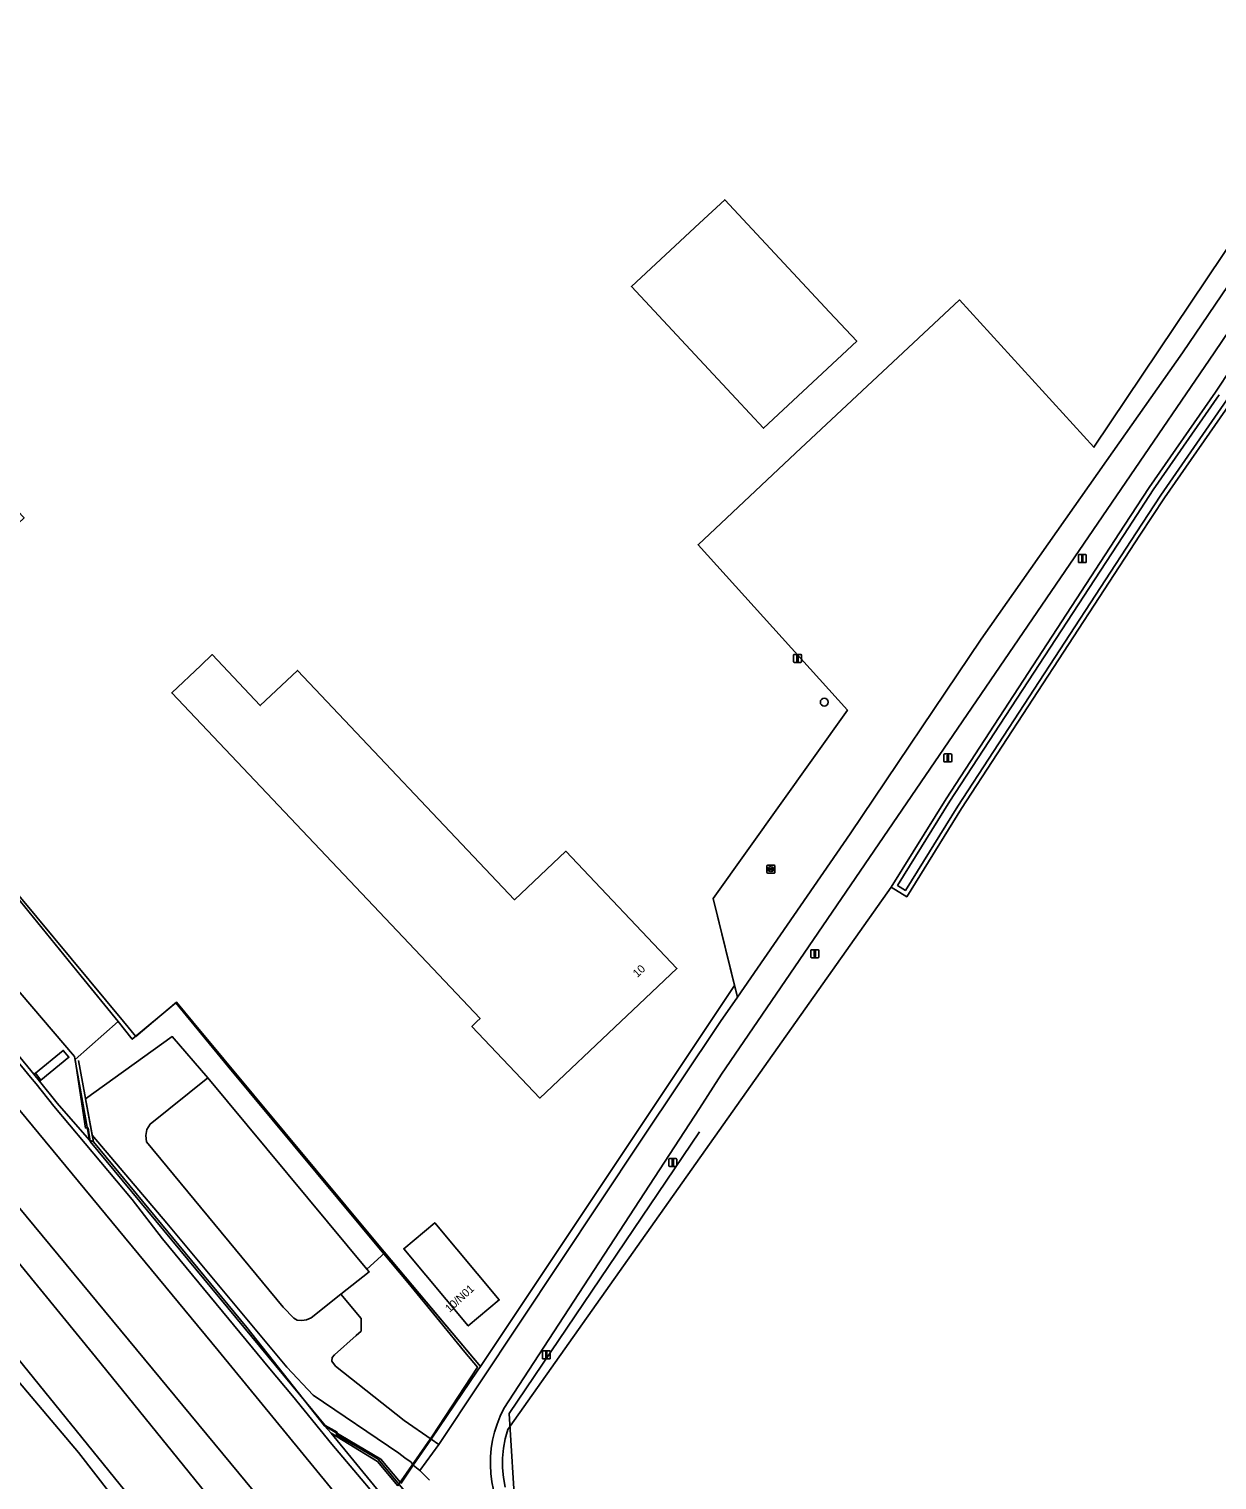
# Model space of a CAD drawing. Extents: x 158132 to 159664, y 385256 to 387218.
# Drawn here: x 158916.2 to 159064.7, y 385692.7 to 385874 of the extents above; entities that cross this region are included whole.
import ezdxf

# ---------------------------------------------------------------- set-up
doc = ezdxf.new("R2010")
doc.units = 0
for name, color, linetype in [('IMGEO_Berm_groen', 7, 'Continuous'), ('IMGEO_Boom', 7, 'Continuous'), ('IMGEO_Erf', 7, 'Continuous'), ('IMGEO_Gemengd_bos', 7, 'Continuous'), ('IMGEO_Grasland_overig', 7, 'Continuous'), ('IMGEO_Groenvoorziening', 7, 'Continuous'), ('IMGEO_Hek', 7, 'Continuous'), ('IMGEO_Lichtmast', 7, 'Continuous'), ('IMGEO_Muur', 7, 'Continuous'), ('IMGEO_Oever', 7, 'Continuous'), ('IMGEO_Pand', 7, 'Continuous'), ('IMGEO_Pand_nummerreeks', 7, 'Continuous'), ('IMGEO_Rijbaan_lokaal_gesloten', 7, 'Continuous'), ('IMGEO_Rijbaan_lokaal_open', 7, 'Continuous'), ('IMGEO_Rioolput', 7, 'Continuous'), ('IMGEO_Spoor', 7, 'Continuous'), ('IMGEO_Spoorbaan_halfverhard', 7, 'Continuous'), ('IMGEO_Terreindeel_gesloten', 7, 'Continuous'), ('IMGEO_Terreindeel_open', 7, 'Continuous'), ('IMGEO_Voetpad_op_trap', 7, 'Continuous'), ('IMGEO_Waterloop', 7, 'Continuous')]:
    doc.layers.add(name, color=color, linetype=linetype)

msp = doc.modelspace()

# ---------------------------------------------------------------- linework, layer by layer
at = {"layer": 'IMGEO_Berm_groen'}
for points in [[(159172.92, 385994.15), (159064.3, 385833.55), (159053.26, 385817.37), (159007.27, 385750), (159002.78, 385743.42), (159000, 385739.15), (158975.57, 385701.68)], [(159023.96, 385766.81), (159030.82, 385777.84), (159053.11, 385812.01), (159056.21, 385816.73), (159064.47, 385828.62), (159068.55, 385834.77)], [(158975.73, 385691.84), (158975.51, 385693.04), (158975.4, 385694.25), (158975.4, 385695.47), (158975.51, 385696.69), (158975.74, 385697.89), (158976.08, 385699.06), (158976.35, 385699.45), (159023.96, 385766.81)]]:
    msp.add_lwpolyline(points, dxfattribs=at)
msp.add_lwpolyline([(159002.63, 385749.99), (159004.75, 385753.06), (159004.39, 385754.5), (158972.66, 385706.93), (158972.33, 385706.44), (158966.47, 385697.83), (158967.43, 385697.18), (158992.66, 385735.04)], close=True, dxfattribs=at)
msp.add_arc((158988.64, 385694.83), 14.76, 152.3355, 217.6377, dxfattribs=at)
at = {"layer": 'IMGEO_Boom'}
msp.add_circle((159015.6, 385789.9), 0.489, dxfattribs=at)
at = {"layer": 'IMGEO_Erf'}
msp.add_lwpolyline([(158932.07, 385908.86), (158908.62, 385873.86), (158907.24, 385871.01), (158906.36, 385869.7), (158903.84, 385865.93), (158887.87, 385842.1), (158915.63, 385812.94), (158893.29, 385791.82), (158928.04, 385750), (158929.58, 385748.15), (158931.8, 385750), (158934.69, 385752.42), (158936.69, 385750), (158959.74, 385722.26), (158960.7, 385721.13), (158972.66, 385706.93), (159004.39, 385754.5), (159001.72, 385765.38), (159018.49, 385788.89), (158999.83, 385809.57), (159012.02, 385820.99), (159032.5, 385840.15), (159049.28, 385821.74), (159069.43, 385851.76)], dxfattribs=at)
for points in [[(159003.16, 385852.67), (159016.25, 385838.64), (159019.66, 385834.98), (159008.01, 385824.12), (159004.6, 385827.78), (159000, 385832.71), (158991.51, 385841.82), (159000, 385849.73)], [(158976.92, 385765.21), (158983.32, 385771.28), (158997.19, 385756.65), (158991.67, 385751.42), (158990.17, 385750), (158980.07, 385740.44), (158971.58, 385749.4), (158972.21, 385750), (158972.61, 385750.37), (158934.07, 385791.05), (158937.7, 385794.49), (158939.12, 385795.84), (158945.14, 385789.48), (158949.77, 385793.86)], [(158975, 385715.22), (158971.13, 385711.98), (158963.07, 385721.63), (158966.94, 385724.86)]]:
    msp.add_lwpolyline(points, close=True, dxfattribs=at)
at = {"layer": 'IMGEO_Gemengd_bos'}
for points in [[(159069.43, 385851.76), (159049.28, 385821.74), (159032.5, 385840.15), (159012.02, 385820.99), (158999.83, 385809.57), (159018.49, 385788.89), (159001.72, 385765.38), (159004.39, 385754.5), (159004.75, 385753.06), (159018.83, 385773.47), (159035.21, 385797.79), (159050.84, 385820.03), (159060.35, 385833.55), (159088.01, 385874.32), (158987.13, 385983.76)], [(159066.38, 385827.33), (159058.12, 385815.44), (159055.04, 385810.75), (159032.76, 385776.6), (159025.91, 385765.6), (159023.96, 385766.81), (158976.35, 385699.45), (158976.08, 385699.06), (158975.74, 385697.89), (158975.51, 385696.69), (158975.4, 385695.47), (158975.4, 385694.25), (158975.51, 385693.04), (158975.73, 385691.84)]]:
    msp.add_lwpolyline(points, dxfattribs=at)
at = {"layer": 'IMGEO_Grasland_overig'}
for points in [[(158909.76, 385759.85), (158921.92, 385745.65), (158921.97, 385745.39), (158923.8, 385735.18), (158924.3, 385734.97), (158924.14, 385735.79), (158923.3, 385740.36), (158934.14, 385748.13), (158938.59, 385742.97), (158958.45, 385719.07), (158960.7, 385721.13), (158959.74, 385722.26), (158936.69, 385750), (158934.69, 385752.42), (158931.8, 385750), (158929.58, 385748.15), (158928.04, 385750), (158893.29, 385791.82)], [(158885.26, 385781.94), (158916.87, 385743.41), (158917.04, 385743.55), (158920.53, 385746.4), (158921.23, 385745.55), (158917.73, 385742.69), (158917.56, 385742.56), (158919.78, 385739.8), (158923.8, 385735.18), (158921.97, 385745.39), (158921.92, 385745.65), (158909.76, 385759.85)], [(158962.32, 385692.02), (158959.8, 385695.06), (158953.98, 385698.58), (158991.95, 385652.3)]]:
    msp.add_lwpolyline(points, dxfattribs=at)
for points in [[(158917.04, 385743.55), (158916.87, 385743.41), (158917.56, 385742.56), (158917.73, 385742.69)], [(158962.73, 385692.34), (158964.26, 385694.58), (158963.98, 385694.97), (158963.22, 385695.51), (158962.45, 385696.07), (158951.75, 385703.32), (158948.44, 385706.84), (158933.46, 385724.83), (158924.14, 385735.79), (158924.3, 385734.97), (158943.45, 385711.79), (158953.18, 385699.51), (158960.22, 385695.34), (158962.61, 385692.47)], [(158962.32, 385692.02), (158962.61, 385692.47), (158960.22, 385695.34), (158953.18, 385699.51), (158953.98, 385698.58), (158959.8, 385695.06)]]:
    msp.add_lwpolyline(points, close=True, dxfattribs=at)
at = {"layer": 'IMGEO_Groenvoorziening'}
msp.add_lwpolyline([(158966.27, 385692.72), (158965.06, 385693.92), (158964.26, 385694.58), (158962.73, 385692.34)], dxfattribs=at)
at = {"layer": 'IMGEO_Hek'}
for points in [[(159069.43, 385851.76), (159049.28, 385821.74)], [(159049.28, 385821.74), (159032.5, 385840.15), (159012.02, 385820.99)], [(159004.75, 385753.06), (159001.72, 385765.38), (159018.49, 385788.89), (158999.83, 385809.57), (159012.02, 385820.99)], [(158928.04, 385750), (158893.29, 385791.82)], [(158962.46, 385692.22), (158966.65, 385698.25), (158972.27, 385706.81), (158970.71, 385708.7), (158967.57, 385712.53), (158963.6, 385717.37), (158960.36, 385721.23), (158941.08, 385744.42), (158934.61, 385752.33), (158929.15, 385747.79), (158927.4, 385749.99), (158922.76, 385755.66), (158916.28, 385763.67), (158904.84, 385777.67), (158898.32, 385785.62), (158893.43, 385791.54)], [(158931.8, 385750), (158934.69, 385752.42), (158936.69, 385750)], [(158927.4, 385749.99), (158922, 385745.28), (158923.32, 385736.7), (158923.64, 385736.74)], [(158928.04, 385750), (158929.58, 385748.15)], [(158931.8, 385750), (158929.58, 385748.15)], [(158936.69, 385750), (158959.74, 385722.26)], [(158923.64, 385736.74), (158923.89, 385735.02), (158934.11, 385722.7), (158950.08, 385703.36), (158953.23, 385699.54), (158954.73, 385698.69), (158954.61, 385698.43), (158959.85, 385695.35), (158967.8, 385685.8), (158975.82, 385676.2), (158983.82, 385666.58), (158993.47, 385655.01), (159001.45, 385645.37), (159015.71, 385628.27), (159022.08, 385620.55), (159030.13, 385610.93), (159041.19, 385597.53), (159065.26, 385568.73), (159079.54, 385551.51), (159087.54, 385541.87), (159092.37, 385536.15), (159099.04, 385528.11)], [(159000, 385736.24), (158976.25, 385701.04), (158977.04, 385688.31), (158984.03, 385678.97), (159000, 385658.97)], [(158959.74, 385722.26), (158972.66, 385706.93), (158972.33, 385706.44)], [(158972.33, 385706.44), (158966.47, 385697.83)], [(158966.47, 385697.83), (158964.26, 385694.58)], [(158964.26, 385694.58), (158962.69, 385692.28)]]:
    msp.add_lwpolyline(points, dxfattribs=at)
at = {"layer": 'IMGEO_Lichtmast'}
for p, q in [((159047.34, 385807.43), (159047.34, 385808.23)), ((159047.34, 385808.23), (159047.34, 385807.43)), ((159047.44, 385808.33), (159048.23, 385808.33)), ((159048.23, 385808.33), (159047.44, 385808.33)), ((159048.33, 385808.23), (159048.33, 385807.43)), ((159048.33, 385807.43), (159048.33, 385808.23)), ((159048.23, 385807.33), (159047.44, 385807.33)), ((159047.44, 385807.33), (159048.23, 385807.33)), ((159011.77, 385794.97), (159011.77, 385795.77)), ((159011.77, 385795.77), (159011.77, 385794.97)), ((159011.87, 385795.87), (159012.66, 385795.87)), ((159012.66, 385795.87), (159011.87, 385795.87)), ((159012.76, 385795.77), (159012.76, 385794.97)), ((159012.76, 385794.97), (159012.76, 385795.77)), ((159012.66, 385794.87), (159011.87, 385794.87)), ((159011.87, 385794.87), (159012.66, 385794.87)), ((159030.53, 385782.53), (159030.53, 385783.33)), ((159030.53, 385783.33), (159030.53, 385782.53)), ((159030.63, 385783.43), (159031.42, 385783.43)), ((159031.42, 385783.43), (159030.63, 385783.43)), ((159031.42, 385782.43), (159030.63, 385782.43)), ((159030.63, 385782.43), (159031.42, 385782.43)), ((159031.52, 385783.33), (159031.52, 385782.53)), ((159031.52, 385782.53), (159031.52, 385783.33)), ((159013.92, 385758.08), (159013.92, 385758.88)), ((159013.92, 385758.88), (159013.92, 385758.08)), ((159014.02, 385758.98), (159014.81, 385758.98)), ((159014.81, 385758.98), (159014.02, 385758.98)), ((159014.91, 385758.88), (159014.91, 385758.08)), ((159014.91, 385758.08), (159014.91, 385758.88)), ((159014.81, 385757.98), (159014.02, 385757.98)), ((159014.02, 385757.98), (159014.81, 385757.98)), ((158996.18, 385732), (158996.18, 385732.8)), ((158996.18, 385732.8), (158996.18, 385732)), ((158996.28, 385732.9), (158997.07, 385732.9)), ((158997.07, 385732.9), (158996.28, 385732.9)), ((158997.07, 385731.9), (158996.28, 385731.9)), ((158996.28, 385731.9), (158997.07, 385731.9)), ((158997.17, 385732.8), (158997.17, 385732)), ((158997.17, 385732), (158997.17, 385732.8)), ((158980.38, 385707.95), (158980.38, 385708.75)), ((158980.38, 385708.75), (158980.38, 385707.95)), ((158980.48, 385708.85), (158981.27, 385708.85)), ((158981.27, 385708.85), (158980.48, 385708.85)), ((158981.37, 385708.75), (158981.37, 385707.95)), ((158981.37, 385707.95), (158981.37, 385708.75)), ((158981.27, 385707.85), (158980.48, 385707.85)), ((158980.48, 385707.85), (158981.27, 385707.85))]:
    msp.add_line(p, q, dxfattribs=at)
for points in [[(159047.76, 385808.21), (159047.91, 385808.21), (159047.91, 385807.46), (159047.76, 385807.46), (159047.76, 385808.21)], [(159012.19, 385795.75), (159012.34, 385795.75), (159012.34, 385795), (159012.19, 385795), (159012.19, 385795.75)], [(159030.95, 385783.3), (159031.1, 385783.3), (159031.1, 385782.55), (159030.95, 385782.55), (159030.95, 385783.3)], [(159014.34, 385758.86), (159014.49, 385758.86), (159014.49, 385758.11), (159014.34, 385758.11), (159014.34, 385758.86)], [(158996.6, 385732.77), (158996.75, 385732.77), (158996.75, 385732.02), (158996.6, 385732.02), (158996.6, 385732.77)], [(158980.8, 385708.73), (158980.95, 385708.73), (158980.95, 385707.98), (158980.8, 385707.98), (158980.8, 385708.73)]]:
    msp.add_lwpolyline(points, dxfattribs=at)
for centre, start, end in [((159047.44, 385808.23), 90, 180), ((159047.44, 385808.23), 90, 180), ((159048.23, 385808.23), 0, 90), ((159048.23, 385808.23), 360, 90), ((159047.44, 385807.43), 180, 270), ((159047.44, 385807.43), 180, 270), ((159048.23, 385807.43), 270, 0), ((159048.23, 385807.43), 270, 0), ((159011.87, 385795.77), 90, 180), ((159011.87, 385795.77), 90, 180), ((159012.66, 385795.77), 0, 90), ((159012.66, 385795.77), 360, 90), ((159011.87, 385794.97), 180, 270), ((159011.87, 385794.97), 180, 270), ((159012.66, 385794.97), 270, 0), ((159012.66, 385794.97), 270, 0), ((159030.63, 385783.33), 90, 180), ((159030.63, 385783.33), 90, 180), ((159030.63, 385782.53), 180, 270), ((159030.63, 385782.53), 180, 270), ((159031.42, 385783.33), 0, 90), ((159031.42, 385783.33), 360, 90), ((159031.42, 385782.53), 270, 0), ((159031.42, 385782.53), 270, 0), ((159014.02, 385758.88), 90, 180), ((159014.02, 385758.88), 90, 180), ((159014.81, 385758.88), 0, 90), ((159014.81, 385758.88), 360, 90), ((159014.02, 385758.08), 180, 270), ((159014.02, 385758.08), 180, 270), ((159014.81, 385758.08), 270, 0), ((159014.81, 385758.08), 270, 0), ((158996.28, 385732.8), 90, 180), ((158996.28, 385732.8), 90, 180), ((158996.28, 385732), 180, 270), ((158996.28, 385732), 180, 270), ((158997.07, 385732.8), 0, 90), ((158997.07, 385732.8), 360, 90), ((158997.07, 385732), 270, 0), ((158997.07, 385732), 270, 0), ((158980.48, 385708.75), 90, 180), ((158980.48, 385708.75), 90, 180), ((158981.27, 385708.75), 0, 90), ((158981.27, 385708.75), 360, 90), ((158980.48, 385707.95), 180, 270), ((158980.48, 385707.95), 180, 270), ((158981.27, 385707.95), 270, 0), ((158981.27, 385707.95), 270, 0)]:
    msp.add_arc(centre, 0.1, start, end, dxfattribs=at)
at = {"layer": 'IMGEO_Muur'}
msp.add_lwpolyline([(158962.61, 385692.47), (158960.22, 385695.34), (158953.18, 385699.51), (158943.45, 385711.79), (158924.3, 385734.97), (158922.42, 385745.12)], dxfattribs=at)
at = {"layer": 'IMGEO_Oever'}
for points in [[(159068.55, 385834.77), (159064.47, 385828.62), (159056.21, 385816.73), (159053.11, 385812.01), (159030.82, 385777.84), (159023.96, 385766.81), (159025.91, 385765.6), (159032.76, 385776.6), (159055.04, 385810.75), (159058.12, 385815.44), (159066.38, 385827.33)], [(159065.9, 385827.65), (159057.64, 385815.76), (159054.56, 385811.06), (159032.27, 385776.91), (159025.73, 385766.39), (159024.75, 385767), (159031.3, 385777.53), (159053.59, 385811.7), (159056.69, 385816.41), (159064.95, 385828.3)]]:
    msp.add_lwpolyline(points, dxfattribs=at)
at = {"layer": 'IMGEO_Pand'}
for points in [[(159016.25, 385838.64), (159003.16, 385852.67), (159000, 385849.73), (158991.51, 385841.82), (159000, 385832.71), (159004.6, 385827.78), (159008.01, 385824.12), (159019.66, 385834.98)], [(158997.19, 385756.65), (158983.32, 385771.28), (158976.92, 385765.21), (158949.77, 385793.86), (158945.14, 385789.48), (158939.12, 385795.84), (158937.7, 385794.49), (158934.07, 385791.05), (158972.61, 385750.37), (158972.21, 385750), (158971.58, 385749.4), (158980.07, 385740.44), (158990.17, 385750), (158991.67, 385751.42)], [(158938.59, 385742.97), (158931.38, 385737.2), (158930.95, 385736.51), (158930.83, 385735.75), (158930.92, 385734.96), (158948, 385714.31), (158949.32, 385712.94), (158949.75, 385712.7), (158950.34, 385712.65), (158950.93, 385712.74), (158951.5, 385712.99), (158955.2, 385715.93), (158958.73, 385718.73), (158958.45, 385719.07)], [(158971.13, 385711.98), (158975, 385715.22), (158966.94, 385724.86), (158963.07, 385721.63)]]:
    msp.add_lwpolyline(points, close=True, dxfattribs=at)
at = {"layer": 'IMGEO_Rijbaan_lokaal_gesloten'}
for points in [[(159176.42, 385996.19), (159172.48, 386000.3), (159172.43, 385999.29), (159172.11, 385998.23), (159168.48, 385992.87), (159167.77, 385991.84), (159128.6, 385934.11), (159088.01, 385874.32), (159060.35, 385833.55), (159050.84, 385820.03), (159035.21, 385797.79), (159018.83, 385773.47), (159004.75, 385753.06), (159002.63, 385749.99), (158992.66, 385735.04), (158967.43, 385697.18), (158965.06, 385693.92), (158966.27, 385692.72)], [(158975.57, 385701.68), (159000, 385739.15), (159002.78, 385743.42), (159007.27, 385750), (159053.26, 385817.37), (159064.3, 385833.55), (159172.92, 385994.15)]]:
    msp.add_lwpolyline(points, dxfattribs=at)
msp.add_arc((158988.64, 385694.83), 14.76, 152.3355, 217.6377, dxfattribs=at)
at = {"layer": 'IMGEO_Rijbaan_lokaal_open'}
msp.add_lwpolyline([(158966.47, 385697.83), (158964.26, 385694.58), (158965.06, 385693.92), (158967.43, 385697.18)], close=True, dxfattribs=at)
at = {"layer": 'IMGEO_Rioolput'}
for p, q in [((159008.43, 385768.61), (159008.43, 385769.47)), ((159008.5, 385769.54), (159009.35, 385769.54)), ((159009.35, 385768.54), (159008.5, 385768.54)), ((159008.68, 385769.03), (159008.68, 385769.05)), ((159009.12, 385769), (159008.72, 385769)), ((159008.73, 385769.08), (159009.13, 385769.08)), ((159008.91, 385769.32), (159008.94, 385769.32)), ((159008.94, 385768.76), (159008.91, 385768.76)), ((159009.17, 385769.05), (159009.17, 385769.03)), ((159009.43, 385769.47), (159009.43, 385768.61))]:
    msp.add_line(p, q, dxfattribs=at)
for points in [[(159008.43, 385768.61), (159008.43, 385769.47)], [(159008.5, 385769.54), (159009.35, 385769.54)], [(159009.35, 385768.54), (159008.5, 385768.54)], [(159009.43, 385769.47), (159009.43, 385768.61)]]:
    msp.add_lwpolyline(points, dxfattribs=at)
for centre, radius, start, end in [((159008.5, 385769.46), 0.0765, 91.552, 178.448), ((159008.5, 385769.46), 0.0765, 91.552, 178.448), ((159008.5, 385768.62), 0.0765, 181.552, 268.448), ((159008.5, 385768.62), 0.0765, 181.552, 268.448), ((159008.73, 385769.04), 0.0403, 85.8775, 175.7526), ((159008.72, 385769.03), 0.0366, 178.938, 274.7102), ((159009.13, 385769.04), 0.043, 264.8664, 352.4533), ((159009.13, 385769.04), 0.0386, 1.7309, 96.639), ((159009.35, 385769.46), 0.0765, 1.552, 88.448), ((159009.35, 385769.46), 0.0765, 1.552, 88.448), ((159009.35, 385768.62), 0.0765, 271.552, 358.448), ((159009.35, 385768.62), 0.0765, 271.552, 358.448)]:
    msp.add_arc(centre, radius, start, end, dxfattribs=at)
for centre, major_axis, ratio, start_param, end_param in [((159008.91, 385769.04), (-0.387, 0.002), 0.722429, 4.712389, 7.853982), ((159008.94, 385769.04), (-0.39, 0.002), 0.717154, 1.570796, 4.712389)]:
    msp.add_ellipse(centre, major_axis=major_axis, ratio=ratio, start_param=start_param, end_param=end_param, dxfattribs=at)
at = {"layer": 'IMGEO_Spoor'}
for points in [[(158183.23, 386593.64), (158250.34, 386512.27), (158320.88, 386427.2), (158390.63, 386342.73), (158437.14, 386286.56), (158475.32, 386240.27), (158493.61, 386217.92), (158666.6, 386008.62), (158712.98, 385952.66), (158746.85, 385911.48), (158804.33, 385842.16), (158903.44, 385721.96), (158968.31, 385641.91), (158993.3, 385610.47), (159052.26, 385536.6), (159079.06, 385503.44), (159104.74, 385472.03), (159179.39, 385381.3), (159222.18, 385329.69), (159276.78, 385263.61)], [(158305.02, 386458.21), (158323.8, 386435.6), (158392.22, 386352.85), (158899.46, 385738.82), (158924.54, 385708.13), (158959.68, 385664.77), (158977.24, 385642.93), (159021.11, 385587.17), (159057.71, 385540.32), (159087.55, 385502.29), (159118.56, 385463.18), (159158.87, 385413.29), (159192.22, 385372.58), (159280.07, 385266.34)], [(158391.09, 386360.72), (158491.13, 386239.56), (158538.07, 386183.03), (158587.16, 386123.49), (158724.17, 385957.81), (158781.97, 385887.68), (158833.11, 385825.86), (158873.91, 385776.35), (158947.25, 385687.78), (158974.98, 385654.09), (158999.8, 385623.89), (159031.62, 385584.85), (159070.24, 385536.67), (159150.39, 385436.4), (159181.35, 385398.01), (159212.16, 385360.43), (159269.58, 385291.16), (159286.01, 385271.25)], [(158467.76, 386280.04), (158481.71, 386263.38), (158516.18, 386221.44), (158744.02, 385945.82), (158789.16, 385891.01), (158837.92, 385832.2), (158939.86, 385708.89), (158979.91, 385660.12), (159034.3, 385592.75), (159082.74, 385531.41), (159124.36, 385478.04), (159172.25, 385417.35), (159208.96, 385371.65), (159261.54, 385307.65), (159289.31, 385273.98)]]:
    msp.add_lwpolyline(points, dxfattribs=at)
at = {"layer": 'IMGEO_Spoorbaan_halfverhard'}
for points in [[(158598, 386087.5), (158730.91, 385924.9), (158787.27, 385858.58), (158841.08, 385793.16), (158865.33, 385763.67), (158922.41, 385696.17), (159008.49, 385585.24)], [(158962.53, 385687.2), (158954.07, 385697.22), (158949.18, 385703.24), (158946.33, 385706.62), (158932.93, 385722.87), (158929.12, 385727.78), (158919.35, 385739.45), (158917.14, 385742.21), (158916.44, 385743.06), (158884.84, 385781.59), (158878.45, 385789.3), (158868.97, 385800.77), (158842.32, 385832.69), (158825.45, 385853.53), (158800.24, 385883.86), (158788.4, 385898.17), (158694.95, 386011.19)]]:
    msp.add_lwpolyline(points, dxfattribs=at)
at = {"layer": 'IMGEO_Terreindeel_gesloten'}
for points in [[(158694.95, 386011.19), (158788.4, 385898.17), (158800.24, 385883.86), (158825.45, 385853.53), (158842.32, 385832.69), (158868.97, 385800.77), (158878.45, 385789.3), (158884.84, 385781.59), (158916.44, 385743.06), (158917.14, 385742.21), (158919.35, 385739.45), (158929.12, 385727.78), (158932.93, 385722.87), (158946.33, 385706.62), (158949.18, 385703.24), (158954.07, 385697.22), (158962.53, 385687.2)], [(158991.95, 385652.3), (158953.98, 385698.58), (158953.18, 385699.51), (158943.45, 385711.79), (158924.3, 385734.97), (158923.8, 385735.18), (158919.78, 385739.8), (158917.56, 385742.56), (158916.87, 385743.41), (158885.26, 385781.94), (158882.5, 385785.27), (158881.87, 385786.04), (158881.1, 385786.96), (158880.46, 385787.73), (158878.87, 385789.65), (158869.39, 385801.12), (158755.94, 385938.26), (158735.25, 385963.49), (158696.82, 386010.09)]]:
    msp.add_lwpolyline(points, dxfattribs=at)
at = {"layer": 'IMGEO_Terreindeel_open'}
for points in [[(158966.47, 385697.83), (158963.13, 385700.18), (158954.54, 385706.95), (158954.08, 385707.58), (158954.14, 385708.02), (158954.41, 385708.37), (158957.11, 385710.78), (158957.74, 385711.34), (158957.73, 385712.89), (158955.2, 385715.93), (158951.5, 385712.99), (158950.93, 385712.74), (158950.34, 385712.65), (158949.75, 385712.7), (158949.32, 385712.94), (158948, 385714.31), (158930.92, 385734.96), (158930.83, 385735.75), (158930.95, 385736.51), (158931.38, 385737.2), (158938.59, 385742.97), (158934.14, 385748.13), (158923.3, 385740.36), (158924.14, 385735.79), (158933.46, 385724.83), (158948.44, 385706.84), (158951.75, 385703.32), (158962.45, 385696.07), (158963.22, 385695.51), (158963.98, 385694.97), (158964.26, 385694.58)], [(158954.14, 385708.02), (158954.08, 385707.58), (158954.54, 385706.95), (158963.13, 385700.18), (158966.47, 385697.83), (158972.33, 385706.44), (158972.66, 385706.93), (158960.7, 385721.13), (158958.45, 385719.07), (158958.73, 385718.73), (158955.2, 385715.93), (158957.73, 385712.89), (158957.74, 385711.34), (158957.11, 385710.78), (158954.41, 385708.37)]]:
    msp.add_lwpolyline(points, close=True, dxfattribs=at)
at = {"layer": 'IMGEO_Voetpad_op_trap'}
msp.add_lwpolyline([(158917.73, 385742.69), (158921.23, 385745.55), (158920.53, 385746.4), (158917.04, 385743.55)], close=True, dxfattribs=at)
at = {"layer": 'IMGEO_Waterloop'}
msp.add_lwpolyline([(159064.95, 385828.3), (159056.69, 385816.41), (159053.59, 385811.7), (159031.3, 385777.53), (159024.75, 385767), (159025.73, 385766.39), (159032.27, 385776.91), (159054.56, 385811.06), (159057.64, 385815.76), (159065.9, 385827.65)], dxfattribs=at)

# ---------------------------------------------------------------- texts
at = {"layer": 'IMGEO_Pand_nummerreeks'}
for s, rotation, p in [('10', 43.4531, (158992.25, 385755.45)), ('10/N01', 42.3989, (158968.78, 385713.6))]:
    msp.add_text(s, height=1, rotation=rotation, dxfattribs=at).set_placement(p)

doc.saveas('drawing.dxf')
